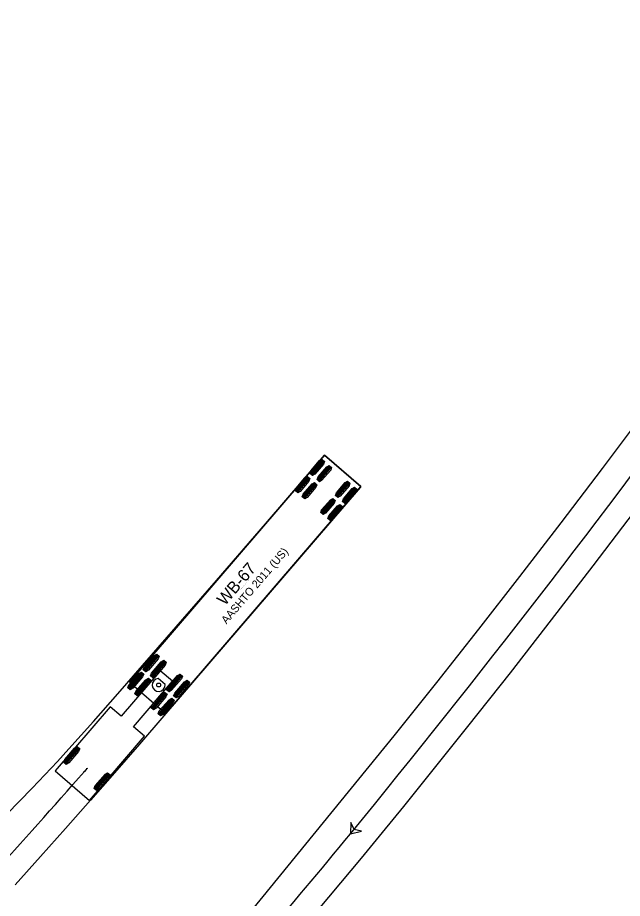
# Model space of a CAD drawing. Extents: x 2175591 to 2194071, y 76570 to 86955.
# Drawn here: x 2176550.3 to 2176657.4, y 77434.5 to 77590.4 of the extents above; entities that cross this region are included whole.
import ezdxf

# ---------------------------------------------------------------- set-up
doc = ezdxf.new("R2010")
doc.units = 0
doc.layers.add('C-UTIL-STRM-TEXT', color=7, linetype='Continuous')

msp = doc.modelspace()

# ---------------------------------------------------------------- linework, layer by layer
at = {"layer": 'C-UTIL-STRM-TEXT'}
for p, q in [((2176604.62, 77512.95), (2176570.09, 77472.75)), ((2176602.09, 77509.65), (2176604.24, 77512.16)), ((2176602.26, 77509.5), (2176604.41, 77512.01)), ((2176602.44, 77509.35), (2176604.59, 77511.86)), ((2176611.07, 77507.41), (2176604.62, 77512.95)), ((2176603.34, 77508.58), (2176605.49, 77511.08)), ((2176603.51, 77508.43), (2176605.66, 77510.93)), ((2176603.69, 77508.28), (2176605.84, 77510.78)), ((2176599.48, 77506.62), (2176601.63, 77509.12)), ((2176599.66, 77506.47), (2176601.81, 77508.97)), ((2176599.83, 77506.32), (2176601.98, 77508.82)), ((2176576.53, 77467.21), (2176611.07, 77507.41)), ((2176600.73, 77505.54), (2176602.88, 77508.05)), ((2176600.91, 77505.39), (2176603.06, 77507.9)), ((2176601.08, 77505.24), (2176603.23, 77507.75)), ((2176606.59, 77505.79), (2176608.74, 77508.29)), ((2176606.76, 77505.64), (2176608.91, 77508.14)), ((2176606.94, 77505.49), (2176609.09, 77507.99)), ((2176607.84, 77504.71), (2176609.99, 77507.22)), ((2176608.01, 77504.56), (2176610.17, 77507.07)), ((2176608.19, 77504.41), (2176610.34, 77506.92)), ((2176603.98, 77502.75), (2176606.13, 77505.26)), ((2176604.16, 77502.6), (2176606.31, 77505.11)), ((2176604.33, 77502.45), (2176606.48, 77504.96)), ((2176605.23, 77501.68), (2176607.39, 77504.18)), ((2176605.41, 77501.53), (2176607.56, 77504.03)), ((2176605.58, 77501.38), (2176607.73, 77503.88)), ((2176572.58, 77474.91), (2176574.97, 77477.69)), ((2176572.75, 77474.76), (2176575.14, 77477.54)), ((2176572.92, 77474.61), (2176575.31, 77477.39)), ((2176573.83, 77473.84), (2176576.22, 77476.62)), ((2176574, 77473.69), (2176576.39, 77476.47)), ((2176574.18, 77473.54), (2176576.57, 77476.32)), ((2176575.54, 77474.78), (2176568.64, 77466.74)), ((2176569.84, 77471.73), (2176572.23, 77474.51)), ((2176570.01, 77471.58), (2176572.4, 77474.36)), ((2176577.72, 77472.91), (2176575.54, 77474.78)), ((2176570.09, 77472.75), (2176576.53, 77467.21)), ((2176570.19, 77471.43), (2176572.58, 77474.21)), ((2176570.81, 77464.87), (2176577.72, 77472.91)), ((2176571.09, 77470.65), (2176573.48, 77473.43)), ((2176571.27, 77470.5), (2176573.66, 77473.28)), ((2176571.44, 77470.35), (2176573.83, 77473.13)), ((2176576.4, 77472.34), (2176575.18, 77473.39)), ((2176576.7, 77471.37), (2176579.09, 77474.15)), ((2176576.87, 77471.22), (2176579.26, 77474)), ((2176577.05, 77471.07), (2176579.44, 77473.85)), ((2176577.95, 77470.3), (2176580.34, 77473.08)), ((2176578.12, 77470.15), (2176580.51, 77472.93)), ((2176578.3, 77470), (2176580.69, 77472.78)), ((2176573.96, 77468.18), (2176576.35, 77470.97)), ((2176574.14, 77468.04), (2176576.53, 77470.82)), ((2176574.31, 77467.89), (2176576.7, 77470.67)), ((2176575.21, 77467.11), (2176577.6, 77469.89)), ((2176575.39, 77466.96), (2176577.78, 77469.74)), ((2176575.56, 77466.81), (2176577.95, 77469.59)), ((2176566.69, 77468.41), (2176556.92, 77457.03)), ((2176568.64, 77466.74), (2176566.69, 77468.41)), ((2176576.53, 77467.21), (2176576.53, 77467.21)), ((2176572.76, 77463.2), (2176570.81, 77464.87)), ((2176562.99, 77451.82), (2176572.76, 77463.2)), ((2176558.5, 77458.53), (2176560.89, 77461.31)), ((2176558.68, 77458.38), (2176561.07, 77461.16)), ((2176558.85, 77458.23), (2176561.24, 77461.01)), ((2176556.92, 77457.03), (2176562.99, 77451.82)), ((2176563.88, 77453.91), (2176566.27, 77456.69)), ((2176564.05, 77453.76), (2176566.44, 77456.54)), ((2176564.22, 77453.61), (2176566.61, 77456.39)), ((2176562.99, 77451.82), (2176562.99, 77451.82))]:
    msp.add_line(p, q, dxfattribs=at)
for points in [[(2176582.54, 77421.04), (2176616.93, 77463.27), (2176620.72, 77467.96), (2176624.48, 77472.67), (2176628.23, 77477.39), (2176631.96, 77482.13), (2176639.21, 77491.43), (2176646.53, 77500.95), (2176653.84, 77510.57), (2176661.09, 77520.23), (2176668.29, 77529.94), (2176675.42, 77539.68), (2176682.51, 77549.47), (2176689.53, 77559.3), (2176696.51, 77569.17), (2176703.43, 77579.07), (2176711.25, 77590.38), (2176718.25, 77585.55), (2176718.16, 77585.42), (2176718.16, 77585.42)], [(2176718.16, 77585.42), (2176688.16, 77541.92), (2176681.15, 77532.22), (2176673.98, 77522.43), (2176666.76, 77512.69), (2176659.47, 77502.99), (2176652.12, 77493.33), (2176644.76, 77483.77), (2176637.47, 77474.42), (2176629.96, 77464.91), (2176622.39, 77455.44), (2176618.58, 77450.74), (2176614.82, 77446.13), (2176611.1, 77441.62), (2176607.44, 77437.21), (2176603.2, 77432.15)], [(2176548.37, 77449.41), (2176550.63, 77451.68), (2176552.87, 77453.98), (2176555.1, 77456.33), (2176557.32, 77458.71), (2176559.34, 77460.93), (2176563.71, 77465.8), (2176568.04, 77470.7), (2176576.78, 77480.69), (2176585.49, 77490.73), (2176594.18, 77500.8), (2176604.62, 77512.95), (2176611.07, 77507.41), (2176610.91, 77507.23), (2176610.91, 77507.23)], [(2176610.91, 77507.23), (2176576.19, 77466.81), (2176571.85, 77461.78), (2176567.43, 77456.7), (2176563.17, 77451.84), (2176558.75, 77446.84), (2176554.32, 77441.87), (2176549.86, 77436.89)], [(2176562.56, 77457.46), (2176562.34, 77457.21), (2176562.12, 77456.96)]]:
    msp.add_lwpolyline(points, dxfattribs=at)
for points in [[(2176602.48, 77509.32), (2176602.05, 77509.69), (2176602.22, 77510.15), (2176603.76, 77511.96), (2176604.2, 77512.19), (2176604.63, 77511.82), (2176604.46, 77511.36), (2176602.91, 77509.56)], [(2176603.73, 77508.24), (2176603.3, 77508.61), (2176603.47, 77509.08), (2176605.02, 77510.88), (2176605.45, 77511.12), (2176605.88, 77510.75), (2176605.71, 77510.28), (2176604.16, 77508.48)], [(2176599.87, 77506.28), (2176599.44, 77506.66), (2176599.61, 77507.12), (2176601.16, 77508.92), (2176601.59, 77509.16), (2176602.02, 77508.79), (2176601.85, 77508.32), (2176600.3, 77506.52)], [(2176601.12, 77505.21), (2176600.69, 77505.58), (2176600.86, 77506.04), (2176602.41, 77507.85), (2176602.84, 77508.08), (2176603.27, 77507.71), (2176603.1, 77507.25), (2176601.56, 77505.45)], [(2176606.98, 77505.45), (2176606.55, 77505.82), (2176606.72, 77506.29), (2176608.26, 77508.09), (2176608.7, 77508.33), (2176609.13, 77507.95), (2176608.96, 77507.49), (2176607.41, 77505.69)], [(2176608.23, 77504.38), (2176607.8, 77504.75), (2176607.97, 77505.21), (2176609.52, 77507.01), (2176609.95, 77507.25), (2176610.38, 77506.88), (2176610.21, 77506.42), (2176608.66, 77504.61)], [(2176604.37, 77502.42), (2176603.94, 77502.79), (2176604.11, 77503.25), (2176605.66, 77505.05), (2176606.09, 77505.29), (2176606.52, 77504.92), (2176606.35, 77504.46), (2176604.81, 77502.66)], [(2176605.63, 77501.34), (2176605.19, 77501.71), (2176605.36, 77502.18), (2176606.91, 77503.98), (2176607.34, 77504.22), (2176607.78, 77503.85), (2176607.61, 77503.38), (2176606.06, 77501.58)], [(2176572.97, 77474.58), (2176572.53, 77474.95), (2176572.74, 77475.45), (2176574.46, 77477.45), (2176574.92, 77477.73), (2176575.36, 77477.36), (2176575.15, 77476.86), (2176573.43, 77474.85)], [(2176574.22, 77473.5), (2176573.79, 77473.87), (2176573.99, 77474.37), (2176575.71, 77476.38), (2176576.17, 77476.65), (2176576.61, 77476.28), (2176576.41, 77475.78), (2176574.68, 77473.78)], [(2176570.23, 77471.39), (2176569.8, 77471.76), (2176570, 77472.26), (2176571.72, 77474.27), (2176572.19, 77474.54), (2176572.62, 77474.17), (2176572.42, 77473.67), (2176570.7, 77471.67)], [(2176571.48, 77470.31), (2176571.05, 77470.69), (2176571.25, 77471.19), (2176572.97, 77473.19), (2176573.44, 77473.47), (2176573.87, 77473.1), (2176573.67, 77472.59), (2176571.95, 77470.59)], [(2176577.09, 77471.04), (2176576.66, 77471.41), (2176576.86, 77471.91), (2176578.58, 77473.91), (2176579.04, 77474.19), (2176579.48, 77473.82), (2176579.28, 77473.32), (2176577.55, 77471.31)], [(2176578.34, 77469.96), (2176577.91, 77470.33), (2176578.11, 77470.83), (2176579.83, 77472.84), (2176580.3, 77473.11), (2176580.73, 77472.74), (2176580.53, 77472.24), (2176578.81, 77470.24)], [(2176574.35, 77467.85), (2176573.92, 77468.22), (2176574.12, 77468.72), (2176575.84, 77470.73), (2176576.31, 77471), (2176576.74, 77470.63), (2176576.54, 77470.13), (2176574.82, 77468.13)], [(2176575.6, 77466.77), (2176575.17, 77467.15), (2176575.37, 77467.65), (2176577.09, 77469.65), (2176577.56, 77469.93), (2176577.99, 77469.56), (2176577.79, 77469.05), (2176576.07, 77467.05)], [(2176558.89, 77458.19), (2176558.46, 77458.56), (2176558.66, 77459.06), (2176560.38, 77461.07), (2176560.85, 77461.34), (2176561.28, 77460.97), (2176561.08, 77460.47), (2176559.36, 77458.47)], [(2176564.27, 77453.57), (2176563.83, 77453.95), (2176564.04, 77454.45), (2176565.76, 77456.45), (2176566.22, 77456.73), (2176566.66, 77456.36), (2176566.45, 77455.85), (2176564.73, 77453.85)], [(2176609.22, 77445.91), (2176611.16, 77446.37), (2176609.85, 77446.69), (2176609.28, 77447.91)]]:
    msp.add_lwpolyline(points, close=True, dxfattribs=at)
for centre, radius in [((2176575.26, 77472.25), 0.34), ((2176562.56, 77457.46), 0.0417), ((2176562.12, 77456.96), 0.0417), ((2176562.12, 77456.96), 0.0417), ((2176609.22, 77445.91), 0.0417), ((2176609.22, 77445.91), 0.0417)]:
    msp.add_circle(centre, radius, dxfattribs=at)
for centre, radius, start, end in [((2175070.31, 78704.47), 1988.01, 320.72292, 323.82204), ((2176575.26, 77472.25), 1.14, 94.3396, 4.3396), ((2175263.6, 78598.3), 1728.82, 317.03592, 318.68594), ((2175565.42, 78307.45), 1353.43, 318.3541, 320.46417)]:
    msp.add_arc(centre, radius, start, end, dxfattribs=at)

# ---------------------------------------------------------------- texts
for s, height, p in [('AASHTO 2011 (US)', 1.4167, (2176587.26, 77482.95)), ('WB-67', 2.125, (2176586.99, 77486.16)), ('(c) 2019 Transoft Solutions, Inc. All rights reserved.', 0.085, (2176589.48, 77488.74))]:
    msp.add_text(s, height=height, rotation=49.3396, dxfattribs=at).set_placement(p)

doc.saveas('drawing.dxf')
